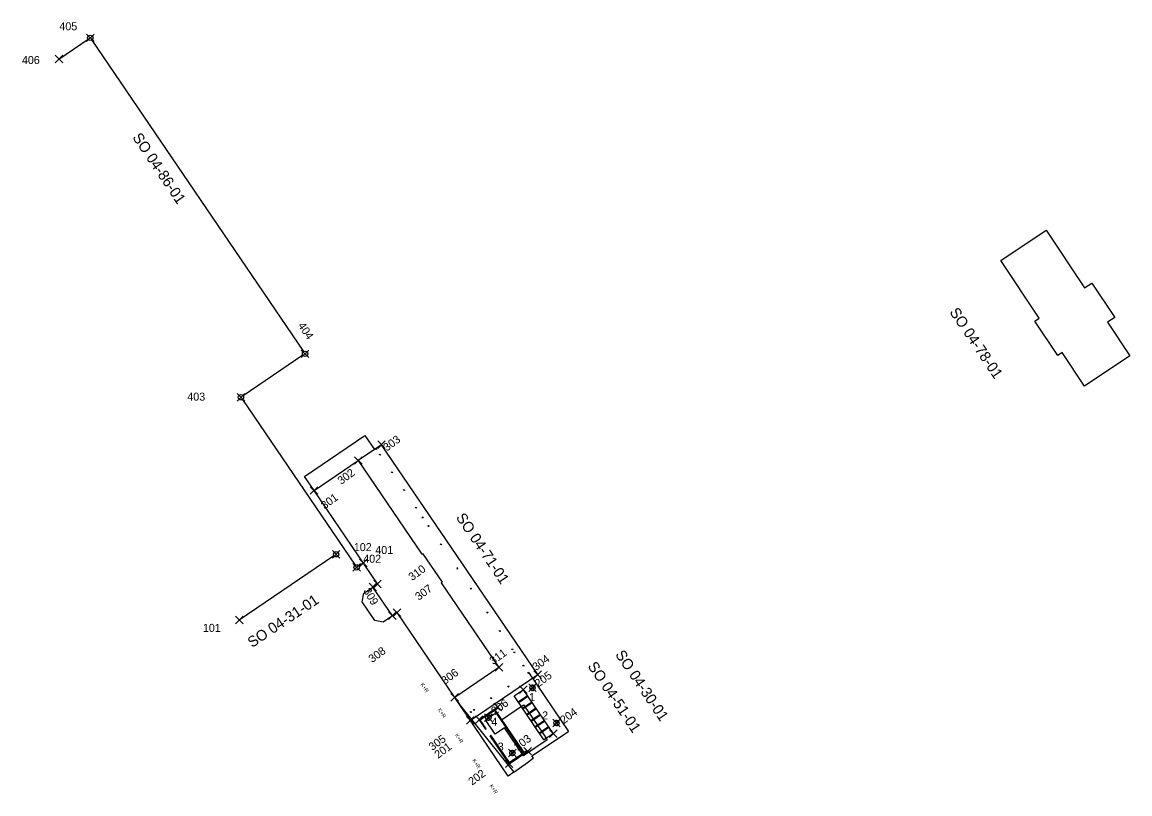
# Model space of a CAD drawing. Extents: x -676190 to -675982, y -1071124 to -1070980.
import ezdxf

# ---------------------------------------------------------------- set-up
doc = ezdxf.new("R2010")
doc.units = 0
for name, color, linetype in [('Default', 7, 'Continuous'), ('SO 04-30-01', 7, 'Continuous'), ('SO 04-30-01_body', 7, 'Continuous'), ('SO 04-31-01', 7, 'Continuous'), ('SO 04-31-01_body', 7, 'Continuous'), ('SO 04-51-01', 7, 'Continuous'), ('SO 04-51-01_body', 7, 'Continuous'), ('SO 04-71-01', 7, 'Continuous'), ('SO 04-71-01_body', 7, 'Continuous'), ('SO 04-78-01', 7, 'Continuous'), ('SO 04-86-01', 7, 'Continuous'), ('SO 04-86-01_body', 7, 'Continuous')]:
    doc.layers.add(name, color=color, linetype=linetype)

# ---------------------------------------------------------------- blocks, each defined once
blk = doc.blocks.new('A$C7abbd9d3')
at = {"layer": 'Default'}
for p, q in [((0.39, 0.14), (-0.39, -0.14)), ((-0.39, -0.14), (0, 0)), ((0, 0), (-0.14, 0.39)), ((0.14, -0.39), (-0.14, 0.39)), ((0, 0), (0, 0)), ((0, 0), (0, 0)), ((0, 0), (0, 0)), ((0, 0), (0.14, -0.39)), ((0, 0), (0, 0)), ((0, 0), (0, 0)), ((0, 0), (0, 0)), ((-0.39, -0.14), (-0.39, -0.14))]:
    blk.add_line(p, q, dxfattribs=at)
blk.add_lwpolyline([(0.39, 0.14), (0.39, 0.14), (0, 0)], dxfattribs=at)
blk.add_circle((0, 0), 0.413, dxfattribs=at)
for start, end in [(110.0552, 200.0552), (290.0552, 20.0552)]:
    blk.add_arc((0, 0), 0.413, start, end, dxfattribs=at)

msp = doc.modelspace()

# ---------------------------------------------------------------- linework, layer by layer
at = {"layer": 'SO 04-30-01_body'}
for p, q in [((-676093.4, -1071105.11), (-676094.82, -1071103.69)), ((-676094.82, -1071105.11), (-676093.4, -1071103.69)), ((-676101.67, -1071110.73), (-676103.09, -1071109.31)), ((-676103.09, -1071110.73), (-676101.67, -1071109.31)), ((-676088.9, -1071111.73), (-676090.32, -1071110.31)), ((-676090.32, -1071111.73), (-676088.9, -1071110.31)), ((-676097.17, -1071117.35), (-676098.59, -1071115.93)), ((-676098.59, -1071117.35), (-676097.17, -1071115.93))]:
    msp.add_line(p, q, dxfattribs=at)
at = {"layer": 'SO 04-31-01'}
msp.add_lwpolyline([(-676131.33, -1071079.65), (-676149.07, -1071091.71)], dxfattribs=at)
msp.add_circle((-676130.91, -1071079.37), 0.5, dxfattribs=at)
at = {"layer": 'SO 04-31-01_body'}
for p, q in [((-676130.2, -1071080.08), (-676131.62, -1071078.66)), ((-676131.62, -1071080.08), (-676130.2, -1071078.66)), ((-676148.36, -1071092.42), (-676149.78, -1071091)), ((-676149.78, -1071092.42), (-676148.36, -1071091))]:
    msp.add_line(p, q, dxfattribs=at)
at = {"layer": 'SO 04-51-01'}
for p, q in [((-676097.57, -1071105.95), (-676095.83, -1071104.77)), ((-676095.83, -1071104.77), (-676090.22, -1071113.02)), ((-676091.96, -1071114.2), (-676097.57, -1071105.95)), ((-676100.63, -1071108.03), (-676104.11, -1071110.39)), ((-676103.9, -1071110.43), (-676101.25, -1071108.63)), ((-676095.8, -1071116.65), (-676101.25, -1071108.63)), ((-676101.13, -1071108.54), (-676100.55, -1071108.15)), ((-676095.67, -1071116.57), (-676101.13, -1071108.54)), ((-676100.55, -1071108.15), (-676100.63, -1071108.03)), ((-676104.11, -1071110.39), (-676102.9, -1071112.17)), ((-676102.77, -1071112.08), (-676103.9, -1071110.43)), ((-676102.9, -1071112.17), (-676102.77, -1071112.08)), ((-676102.05, -1071113.41), (-676101.93, -1071113.32)), ((-676098.48, -1071118.66), (-676102.05, -1071113.41)), ((-676098.45, -1071118.45), (-676101.93, -1071113.32)), ((-676090.39, -1071112.99), (-676090.29, -1071112.92)), ((-676090.32, -1071113.09), (-676090.39, -1071112.99)), ((-676091.93, -1071114.04), (-676091.86, -1071114.14)), ((-676098.48, -1071118.66), (-676095.01, -1071116.3)), ((-676095.8, -1071116.65), (-676098.45, -1071118.45)), ((-676095.09, -1071116.17), (-676095.67, -1071116.57)), ((-676095.01, -1071116.3), (-676095.09, -1071116.17))]:
    msp.add_line(p, q, dxfattribs=at)
for points in [[(-676095.93, -1071104.83), (-676095.87, -1071104.93), (-676095.77, -1071104.87)], [(-676097.5, -1071106.05), (-676097.4, -1071105.98), (-676097.47, -1071105.88)], [(-676095.04, -1071105.94), (-676096.77, -1071107.12)], [(-676094.96, -1071106.06), (-676096.69, -1071107.24)], [(-676094.25, -1071107.1), (-676095.99, -1071108.28)], [(-676094.17, -1071107.22), (-676095.91, -1071108.4)], [(-676093.46, -1071108.26), (-676095.2, -1071109.44)], [(-676093.38, -1071108.37), (-676095.12, -1071109.56)], [(-676092.68, -1071109.42), (-676094.41, -1071110.6)], [(-676092.6, -1071109.53), (-676094.33, -1071110.71)], [(-676091.89, -1071110.57), (-676093.63, -1071111.75)], [(-676091.81, -1071110.69), (-676093.55, -1071111.87)], [(-676091.1, -1071111.73), (-676092.84, -1071112.91)], [(-676091.02, -1071111.85), (-676092.76, -1071113.03)], [(-676090.22, -1071113.02), (-676091.96, -1071114.2)], [(-676092.03, -1071114.1), (-676091.93, -1071114.04)]]:
    msp.add_lwpolyline(points, dxfattribs=at)
at = {"layer": 'SO 04-51-01_body'}
for p, q in [((-676095.12, -1071105.48), (-676096.54, -1071104.06)), ((-676096.54, -1071105.48), (-676095.12, -1071104.06)), ((-676099.92, -1071108.74), (-676101.34, -1071107.32)), ((-676101.34, -1071108.74), (-676099.92, -1071107.32)), ((-676103.4, -1071111.1), (-676104.82, -1071109.68)), ((-676104.82, -1071111.1), (-676103.4, -1071109.68)), ((-676089.51, -1071113.73), (-676090.93, -1071112.31)), ((-676090.93, -1071113.73), (-676089.51, -1071112.31)), ((-676094.3, -1071117.01), (-676095.72, -1071115.59)), ((-676095.72, -1071117.01), (-676094.3, -1071115.59)), ((-676097.77, -1071119.37), (-676099.19, -1071117.95)), ((-676099.19, -1071119.37), (-676097.77, -1071117.95))]:
    msp.add_line(p, q, dxfattribs=at)
at = {"layer": 'SO 04-71-01'}
msp.add_line((-676122.42, -1071058.84), (-676126.77, -1071061.79), dxfattribs=at)
for points in [[(-676136.85, -1071064.78), (-676125.52, -1071057.08)], [(-676125.52, -1071057.08), (-676123.72, -1071059.72)], [(-676108.69, -1071106.22), (-676105.77, -1071110.52), (-676093.14, -1071101.93), (-676122.42, -1071058.84)], [(-676108.69, -1071106.22), (-676119.5, -1071090.31), (-676120.38, -1071090.9), (-676124.04, -1071085.52), (-676123.16, -1071084.93), (-676135.05, -1071067.42), (-676126.77, -1071061.79), (-676114.84, -1071079.34), (-676114.71, -1071079.25), (-676111.07, -1071084.61), (-676111.2, -1071084.7), (-676100.41, -1071100.58), (-676108.69, -1071106.22)], [(-676135.05, -1071067.42), (-676136.85, -1071064.78)], [(-676120.38, -1071090.9), (-676122.13, -1071092.09), (-676123.65, -1071091.8), (-676126.04, -1071088.28), (-676125.74, -1071086.68), (-676124.04, -1071085.52)], [(-676094.78, -1071101.63), (-676087.34, -1071112.58)], [(-676098.67, -1071120.96), (-676108.69, -1071106.22)], [(-676107.84, -1071107.46), (-676097.64, -1071120.25), (-676095.07, -1071118.39), (-676093.95, -1071117.52), (-676094.22, -1071117.17), (-676087.34, -1071112.58)], [(-676092.19, -1071112.93), (-676091.35, -1071114.17), (-676095.81, -1071117.2), (-676099.38, -1071111.95), (-676101.12, -1071113.13), (-676102.94, -1071110.44), (-676100.88, -1071109.04), (-676099.92, -1071110.44), (-676095.79, -1071107.63), (-676092.19, -1071112.93)], [(-676097.64, -1071120.25), (-676098.67, -1071120.96)]]:
    msp.add_lwpolyline(points, dxfattribs=at)
for points in [[(-676123.44, -1071059.72), (-676123.53, -1071059.59), (-676123.4, -1071059.51), (-676123.32, -1071059.63)], [(-676122.7, -1071060.81), (-676122.78, -1071060.69), (-676122.66, -1071060.6), (-676122.58, -1071060.73)], [(-676120.46, -1071064.11), (-676120.54, -1071063.98), (-676120.42, -1071063.9), (-676120.34, -1071064.02)], [(-676118.21, -1071067.42), (-676118.29, -1071067.3), (-676118.17, -1071067.21), (-676118.09, -1071067.34)], [(-676115.96, -1071070.72), (-676116.05, -1071070.6), (-676115.92, -1071070.52), (-676115.84, -1071070.64)], [(-676114.71, -1071072.58), (-676114.79, -1071072.45), (-676114.67, -1071072.37), (-676114.58, -1071072.49)], [(-676113.62, -1071074.18), (-676113.7, -1071074.05), (-676113.58, -1071073.97), (-676113.49, -1071074.09)], [(-676111.28, -1071077.62), (-676111.36, -1071077.5), (-676111.24, -1071077.41), (-676111.15, -1071077.54)], [(-676108.29, -1071082.01), (-676108.21, -1071082.14), (-676108.08, -1071082.05), (-676108.17, -1071081.93)], [(-676105.65, -1071085.91), (-676105.73, -1071085.78), (-676105.61, -1071085.7), (-676105.52, -1071085.82)], [(-676102.6, -1071090.4), (-676102.68, -1071090.27), (-676102.56, -1071090.19), (-676102.47, -1071090.31)], [(-676100.25, -1071093.85), (-676100.33, -1071093.73), (-676100.21, -1071093.64), (-676100.12, -1071093.77)], [(-676097.9, -1071097.3), (-676097.99, -1071097.18), (-676097.86, -1071097.09), (-676097.78, -1071097.22)], [(-676097.52, -1071097.86), (-676097.61, -1071097.74), (-676097.48, -1071097.65), (-676097.4, -1071097.78)], [(-676095.83, -1071100.36), (-676095.91, -1071100.23), (-676095.79, -1071100.15), (-676095.7, -1071100.27)], [(-676094.9, -1071101.72), (-676094.99, -1071101.59), (-676094.86, -1071101.51), (-676094.78, -1071101.63)], [(-676098.68, -1071104.28), (-676098.76, -1071104.16), (-676098.64, -1071104.07), (-676098.56, -1071104.2)], [(-676101.9, -1071106.47), (-676101.99, -1071106.35), (-676101.87, -1071106.26), (-676101.78, -1071106.39)], [(-676105.69, -1071109.05), (-676105.78, -1071108.92), (-676105.65, -1071108.84), (-676105.57, -1071108.96)], [(-676105.11, -1071108.65), (-676105.2, -1071108.53), (-676105.07, -1071108.45), (-676104.99, -1071108.57)]]:
    msp.add_lwpolyline(points, close=True, dxfattribs=at)
at = {"layer": 'SO 04-71-01_body'}
for p, q in [((-676121.71, -1071059.55), (-676123.13, -1071058.13)), ((-676123.13, -1071059.55), (-676121.71, -1071058.13)), ((-676126.06, -1071062.5), (-676127.48, -1071061.08)), ((-676127.48, -1071062.5), (-676126.06, -1071061.08)), ((-676134.34, -1071068.13), (-676135.76, -1071066.71)), ((-676135.76, -1071068.13), (-676134.34, -1071066.71)), ((-676123.33, -1071086.23), (-676124.75, -1071084.81)), ((-676124.75, -1071086.23), (-676123.33, -1071084.81)), ((-676122.45, -1071085.64), (-676123.87, -1071084.22)), ((-676123.87, -1071085.64), (-676122.45, -1071084.22)), ((-676119.67, -1071091.61), (-676121.09, -1071090.19)), ((-676121.09, -1071091.61), (-676119.67, -1071090.19)), ((-676118.79, -1071091.02), (-676120.21, -1071089.6)), ((-676120.21, -1071091.02), (-676118.79, -1071089.6)), ((-676099.7, -1071101.29), (-676101.12, -1071099.87)), ((-676101.12, -1071101.29), (-676099.7, -1071099.87)), ((-676092.43, -1071102.64), (-676093.85, -1071101.22)), ((-676093.85, -1071102.64), (-676092.43, -1071101.22)), ((-676107.98, -1071106.93), (-676109.4, -1071105.51)), ((-676109.4, -1071106.93), (-676107.98, -1071105.51)), ((-676105.06, -1071111.23), (-676106.48, -1071109.81)), ((-676106.48, -1071111.23), (-676105.06, -1071109.81))]:
    msp.add_line(p, q, dxfattribs=at)
at = {"layer": 'SO 04-78-01'}
msp.add_lwpolyline([(-675982.15, -1071042.15), (-675990.66, -1071047.82), (-675994.83, -1071041.56), (-675995.67, -1071042.11), (-675999.96, -1071035.66), (-675999.13, -1071035.11), (-676006.34, -1071024.29), (-675997.83, -1071018.62), (-675990.62, -1071029.44), (-675989.29, -1071028.55), (-675984.99, -1071035), (-675986.32, -1071035.88)], close=True, dxfattribs=at)
at = {"layer": 'SO 04-86-01'}
msp.add_line((-676148.47, -1071050.36), (-676127.36, -1071081.42), dxfattribs=at)
for points in [[(-676182.87, -1070986.52), (-676177.42, -1070982.81)], [(-676176.72, -1070982.94), (-676137.02, -1071041.37)], [(-676137.15, -1071042.06), (-676148.33, -1071049.66)], [(-676126.66, -1071081.55), (-676125.84, -1071080.99)]]:
    msp.add_lwpolyline(points, dxfattribs=at)
for centre in [(-676177.01, -1070982.53), (-676136.74, -1071041.78), (-676148.75, -1071049.94), (-676127.08, -1071081.83)]:
    msp.add_circle(centre, 0.5, dxfattribs=at)
at = {"layer": 'SO 04-86-01_body'}
for p, q in [((-676176.3, -1070983.24), (-676177.72, -1070981.82)), ((-676177.72, -1070983.24), (-676176.3, -1070981.82)), ((-676182.16, -1070987.23), (-676183.58, -1070985.81)), ((-676183.58, -1070987.23), (-676182.16, -1070985.81)), ((-676136.03, -1071042.49), (-676137.45, -1071041.07)), ((-676137.45, -1071042.49), (-676136.03, -1071041.07)), ((-676148.04, -1071050.65), (-676149.46, -1071049.23)), ((-676149.46, -1071050.65), (-676148.04, -1071049.23)), ((-676125.13, -1071081.7), (-676126.55, -1071080.28)), ((-676126.55, -1071081.7), (-676125.13, -1071080.28)), ((-676126.37, -1071082.54), (-676127.79, -1071081.12)), ((-676127.79, -1071082.54), (-676126.37, -1071081.12))]:
    msp.add_line(p, q, dxfattribs=at)

# ---------------------------------------------------------------- block references
at = {"layer": 'SO 04-30-01', "xscale": 1.2113105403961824, "yscale": 1.2113105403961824, "rotation": -75.85657232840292}
for p in [(-676094.11, -1071104.4), (-676102.38, -1071110.02), (-676089.61, -1071111.02), (-676097.88, -1071116.64)]:
    msp.add_blockref('A$C7abbd9d3', p, dxfattribs=at)

# ---------------------------------------------------------------- texts
at = {"layer": 'SO 04-30-01'}
msp.add_text('SO 04-30-01', height=2, rotation=303.9254, dxfattribs=at).set_placement((-676078.68, -1071098.17))
at = {"layer": 'SO 04-30-01_body'}
for s, p in [(' 1', (-676095.31, -1071106.9)), (' 2', (-676092.86, -1071110.34)), (' 4', (-676102.38, -1071111.52)), (' 3', (-676101.18, -1071116.19))]:
    msp.add_text(s, height=1.5, dxfattribs=at).set_placement(p)
at = {"layer": 'SO 04-31-01'}
msp.add_text('SO 04-31-01', height=2, rotation=33.9254, dxfattribs=at).set_placement((-676146.66, -1071096.96))
at = {"layer": 'SO 04-31-01_body'}
for s, p in [(' 102', (-676128.16, -1071078.78)), (' 101', (-676156.45, -1071093.92))]:
    msp.add_text(s, height=1.5, dxfattribs=at).set_placement(p)
at = {"layer": 'SO 04-51-01'}
msp.add_text('SO 04-51-01', height=2, rotation=303.9254, dxfattribs=at).set_placement((-676083.86, -1071100.34))
at = {"layer": 'SO 04-51-01_body'}
for s, p in [(' 205', (-676093.45, -1071104.72)), (' 206', (-676101.61, -1071109.91)), (' 204', (-676088.69, -1071111.59)), (' 203', (-676097.34, -1071116.58)), (' 201', (-676112.26, -1071118.09)), (' 202', (-676105.9, -1071123.12))]:
    msp.add_text(s, height=1.5, rotation=36.6286, dxfattribs=at).set_placement(p)
at = {"layer": 'SO 04-71-01'}
for s, height, rotation, p in [('SO 04-71-01', 2, 303.9254, (-676108.54, -1071072.47)), ('K+R', 0.7, 304.1986, (-676115.14, -1071103.79)), ('K+R', 0.7, 304.1986, (-676111.91, -1071108.54)), ('K+R', 0.7, 304.1986, (-676108.68, -1071113.3)), ('K+R', 0.7, 304.1986, (-676105.44, -1071118.05)), ('K+R', 0.7, 304.1986, (-676102.21, -1071122.81))]:
    msp.add_text(s, height=height, rotation=rotation, dxfattribs=at).set_placement(p)
at = {"layer": 'SO 04-71-01_body'}
for s, rotation, p in [(' 303', 36.4023, (-676121.85, -1071060.46)), (' 302', 36.4023, (-676130.41, -1071066.71)), (' 301', 36.4023, (-676133.54, -1071071.35)), (' 310', 36.4023, (-676117.12, -1071084.75)), (' 309', 300.5937, (-676126.17, -1071085.73)), (' 307', 36.4023, (-676115.88, -1071088.44)), (' 308', 36.4023, (-676124.6, -1071100.12)), (' 311', 36.4023, (-676101.93, -1071100.49)), (' 304', 36.4023, (-676093.89, -1071101.61)), (' 306', 36.4023, (-676110.98, -1071104.2)), (' 305', 36.4023, (-676113.33, -1071116.61))]:
    msp.add_text(s, height=1.5, rotation=rotation, dxfattribs=at).set_placement(p)
at = {"layer": 'SO 04-78-01'}
msp.add_text('SO 04-78-01', height=2, rotation=303.9254, dxfattribs=at).set_placement((-676016.03, -1071033.96))
at = {"layer": 'SO 04-86-01'}
msp.add_text('SO 04-86-01', height=2, rotation=303.9254, dxfattribs=at).set_placement((-676169.19, -1071001.19))
at = {"layer": 'SO 04-86-01_body'}
for s, p in [(' 405', (-676183.35, -1070981.11)), (' 406', (-676190.37, -1070987.44)), (' 403', (-676159.37, -1071050.56)), (' 401', (-676124.13, -1071079.32)), (' 402', (-676126.39, -1071080.96))]:
    msp.add_text(s, height=1.5, dxfattribs=at).set_placement(p)
msp.add_text(' 404', height=1.5, rotation=304.3627, dxfattribs=at).set_placement((-676138.46, -1071036.04))

doc.saveas('drawing.dxf')
